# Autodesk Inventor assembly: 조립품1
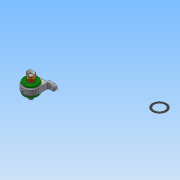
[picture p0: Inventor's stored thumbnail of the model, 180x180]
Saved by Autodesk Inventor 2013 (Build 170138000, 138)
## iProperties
Created: 2019-05
Part Number: 조립품1
Document SubType Name: Assembly
Designer: Administrator
Author: Administrator
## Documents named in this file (13)
- C:\Users\Administrator\Desktop\490504V1003\조립품1.iam
- C:\Users\Administrator\Desktop\490504V1003\개스킷.ipt
- C:\Users\Administrator\Desktop\490504V1003\그리스니플 M6.ipt
- 그리스니플  M6.ipt
- C:\Users\Administrator\Desktop\490504V1003\그리스니플개스킷.ipt
- C:\Users\Administrator\Desktop\490504V1003\베어링너트.ipt
- C:\Users\Administrator\Desktop\490504V1003\본체.ipt
- C:\Users\Administrator\Desktop\490504V1003\볼트 M4.ipt
- C:\Users\Administrator\Desktop\490504V1003\앵귤러 볼 베어링 7205.ipt
- C:\Users\Administrator\Desktop\490504V1003\오일 실 28 40 5 B.ipt
- C:\Users\Administrator\Desktop\490504V1003\축.ipt
- C:\Users\Administrator\Desktop\490504V1003\칼라.ipt
- C:\Users\Administrator\Desktop\490504V1003\커버.ipt
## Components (5 placed, 3 different names)
1. 개스킷:1
2. 그리스니플  M6:1 — 각도:2, 각도:4, 각도:5
3. 그리스니플개스킷:1
4. 개스킷:2
5. 개스킷:3
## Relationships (3: Angle 3)
- 각도:2 [Angle]: 그리스니플  M6:1
- 각도:4 [Angle]: 그리스니플  M6:1
- 각도:5 [Angle]: 그리스니플  M6:1
